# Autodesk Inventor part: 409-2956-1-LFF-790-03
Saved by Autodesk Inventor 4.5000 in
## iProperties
Created: 2010-09
Part Number: 409-2956-1-LFF-790-03
Cost Center: 0 lbmass
Material: A36 STEEL PLATE
Document SubType Name: Sheet Metal
Designer: S. Boerckel
Authority: 0 in^3
Mass: 2019.1 g
Surface Area: 484.956 cm^2
Volume: 256.883 cm^3
Density: 7.86 g/cm^3
Flat Pattern Width: 11.43 cm
Flat Pattern Length: 17.78 cm
Flat Pattern Area: 203.225 cm^2
Sheet Metal Rule: 1/2"Thk
Sheet Metal Width: 7.0000 in
Sheet Metal Length: 31.5000 in^2
Description: WELD PLATE
User Status: MACHINE
SaveDate: 2008-01-15
SaveTime: 10:24
FileName: Sheet Metal
Wide: =<Flat Pattern Width>cm
Length: =<Flat Pattern Length>cm
Thickness: 0.5000 in
SMR: =<Sheet Metal Rule> - <Material>
Author: S. Boerckel
Revision Number: 0
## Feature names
1. Hole1
2. Plate1
